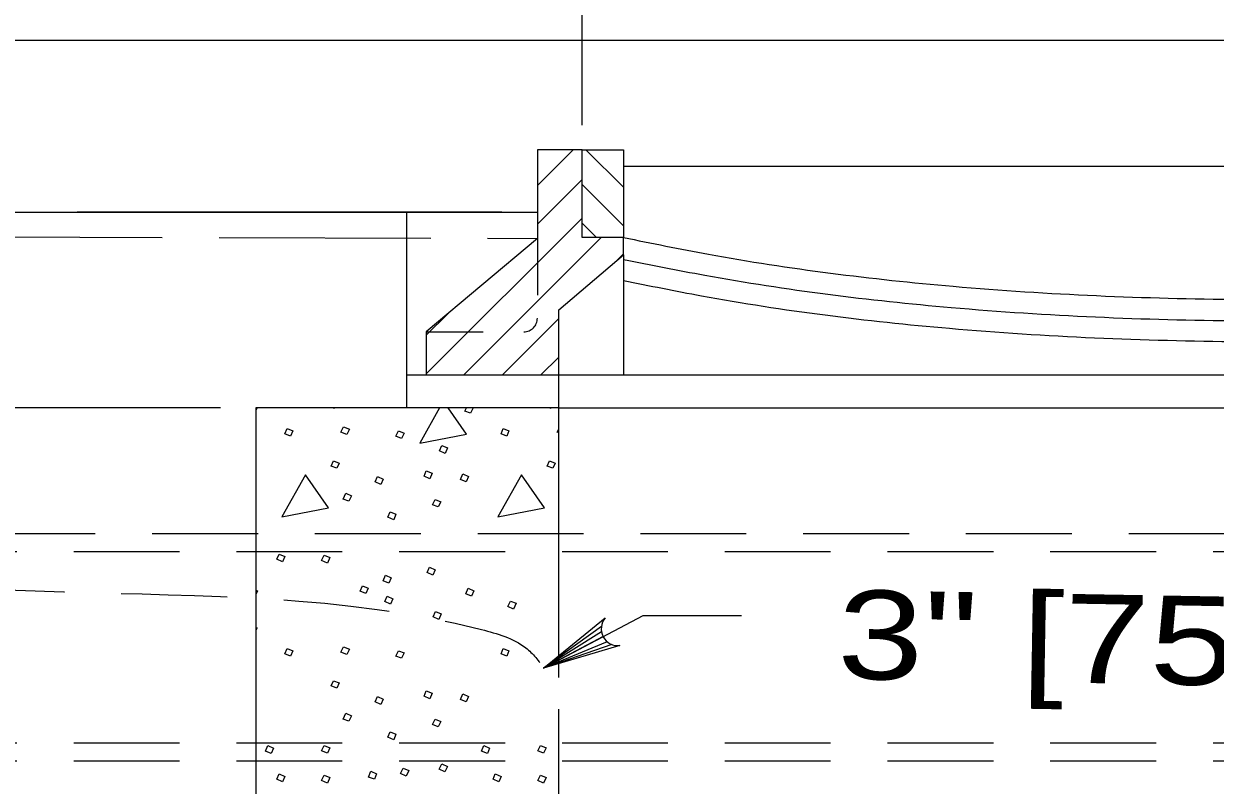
# Model space of a CAD drawing. Extents: x 1083.1 to 1123, y 697.4 to 741.4.
# Drawn here: x 1092.128 to 1094.221, y 724.717 to 726.055 of the extents above; entities that cross this region are included whole.
import ezdxf

# ---------------------------------------------------------------- set-up
doc = ezdxf.new("R2010")
doc.units = 0
doc.header["$LTSCALE"] = 0.062
for name, pattern in [('LONG_DASHED', [7.5, 6, -1.5]), ('MEDIUM_DASHED', [4.5, 3, -1.5]), ('SHORT_DASHED', [2.7, 1.5, -1.2])]:
    doc.linetypes.add(name, pattern=pattern)
doc.layers.add('1', color=7, linetype='Continuous', lineweight=13)

msp = doc.modelspace()

# ---------------------------------------------------------------- linework, layer by layer
at = {"layer": '1'}
for p, q in [((1093.10842, 725.87658), (1093.10842, 726.45525)), ((1093.02983, 725.77058), (1093.09258, 725.83325)), ((1093.18108, 725.7675), (1093.11533, 725.83325)), ((1093.02983, 725.70275), (1093.10842, 725.78125)), ((1093.18108, 725.69958), (1093.10842, 725.77225)), ((1092.8345, 725.4395), (1093.10842, 725.71342)), ((1093.13358, 725.67925), (1093.10842, 725.70442)), ((1092.9005, 725.43767), (1093.14208, 725.67925)), ((1093.18108, 725.67925), (1093.10842, 725.67925)), ((1093.16817, 725.6375), (1093.18108, 725.65042)), ((1092.8345, 725.50733), (1092.87292, 725.54583)), ((1092.96833, 725.43767), (1093.0675, 725.53683)), ((1093.03617, 725.43767), (1093.0675, 725.469)), ((1092.47292, 725.37967), (1091.73158, 725.37967)), ((1092.5375, 725.37967), (1092.53542, 725.37542)), ((1093.14242, 724.99583), (1093.04042, 724.9225)), ((1093.14267, 724.98625), (1093.04042, 724.9225)), ((1093.14567, 724.97792), (1093.04042, 724.9225)), ((1093.15275, 724.969), (1093.04042, 724.9225)), ((1093.16075, 724.96417), (1093.04042, 724.9225))]:
    msp.add_line(p, q, dxfattribs=at)
at = {"layer": '1', "lineweight": 25}
for p, q in [((1093.18108, 725.80433), (1095.37617, 725.80433)), ((1092.96733, 725.7235), (1092.22125, 725.7235)), ((1092.80058, 725.37967), (1092.80058, 725.7235)), ((1093.18108, 725.6485), (1093.18108, 725.43767)), ((1092.80058, 725.43767), (1092.8345, 725.43767)), ((1093.0675, 725.43767), (1095.37617, 725.43767)), ((1093.0675, 725.37967), (1095.442, 725.37967)), ((1093.0675, 724.90642), (1093.0675, 725.37967)), ((1093.0675, 722.82933), (1093.0675, 724.8505))]:
    msp.add_line(p, q, dxfattribs=at)
at = {"layer": '1', "linetype": 'LONG_DASHED', "lineweight": 25}
msp.add_line((1091.9985, 725.68033), (1093.02983, 725.67767), dxfattribs=at)
at = {"layer": '1', "linetype": 'SHORT_DASHED', "lineweight": 25}
for p, q in [((1093.02983, 725.67767), (1093.02983, 725.5375)), ((1092.8345, 725.5135), (1093.00583, 725.5135))]:
    msp.add_line(p, q, dxfattribs=at)
at = {"layer": '1', "linetype": 'MEDIUM_DASHED'}
for p, q in [((1089.92717, 725.12742), (1098.57942, 725.12742)), ((1089.92717, 724.79158), (1098.57942, 724.79158)), ((1089.92717, 724.75958), (1098.57942, 724.75958))]:
    msp.add_line(p, q, dxfattribs=at)
at = {"layer": '1', "lineweight": 25}
for points in [[(1098.22375, 725.23933), (1098.22375, 726.0255), (1090.30608, 726.0255)], [(1086.37042, 725.87725), (1090.30608, 725.7235), (1093.02983, 725.7235)], [(1093.10842, 725.83325), (1093.02983, 725.83325), (1093.02983, 725.67767), (1092.8345, 725.5135), (1092.8345, 725.43767), (1093.0675, 725.43767)], [(1093.10842, 725.67925), (1093.10842, 725.83325), (1093.18108, 725.83325), (1093.18108, 725.67925)], [(1093.0675, 725.37967), (1093.0675, 725.552), (1093.18108, 725.6485), (1093.18108, 725.67925)], [(1093.0675, 725.37967), (1092.53542, 725.37967), (1092.53542, 721.67958), (1095.96625, 721.67958), (1095.96625, 725.37967)]]:
    msp.add_lwpolyline(points, dxfattribs=at)
at = {"layer": '1'}
for points in [[(1092.67308, 725.37967), (1092.67283, 725.379), (1092.67117, 725.37967)], [(1092.858, 725.37967), (1092.82342, 725.31767), (1092.90533, 725.33367), (1092.87308, 725.37967)], [(1092.91733, 725.37967), (1092.91267, 725.37033), (1092.90267, 725.37433), (1092.90517, 725.37967)], [(1093.05292, 725.37967), (1093.05267, 725.379), (1093.051, 725.37967)], [(1093.0675, 725.33583), (1093.06458, 725.337), (1093.0675, 725.34275)], [(1092.53542, 725.05983), (1092.53817, 725.0585), (1092.53542, 725.052)], [(1093.04042, 724.9225), (1093.21592, 725.01492), (1093.38875, 725.01492)], [(1092.53542, 724.99417), (1092.5375, 724.99317), (1092.53542, 724.98892)], [(1093.17475, 724.96217), (1093.04042, 724.9225), (1093.14917, 725.01083)]]:
    msp.add_lwpolyline(points, dxfattribs=at)
for points in [[(1092.59017, 725.34367), (1092.60017, 725.33967), (1092.59617, 725.33033), (1092.58617, 725.33433)], [(1092.6895, 725.34633), (1092.6995, 725.34233), (1092.69483, 725.333), (1092.68483, 725.337)], [(1092.78608, 725.33967), (1092.79608, 725.33567), (1092.79142, 725.32633), (1092.78142, 725.33033)], [(1092.97, 725.34367), (1092.98, 725.33967), (1092.976, 725.33033), (1092.966, 725.33433)], [(1092.86208, 725.31367), (1092.87208, 725.30967), (1092.86808, 725.29967), (1092.85808, 725.30433)], [(1092.6715, 725.287), (1092.6815, 725.283), (1092.6775, 725.27367), (1092.6675, 725.27767)], [(1093.05133, 725.287), (1093.06133, 725.283), (1093.05733, 725.27367), (1093.04733, 725.27767)], [(1092.83475, 725.269), (1092.84475, 725.265), (1092.84075, 725.25508), (1092.83075, 725.25975)], [(1092.62217, 725.26233), (1092.58083, 725.18842), (1092.66283, 725.20442)], [(1092.74875, 725.25908), (1092.75875, 725.25442), (1092.75475, 725.24508), (1092.74475, 725.24975)], [(1092.89867, 725.26375), (1092.90867, 725.25908), (1092.90467, 725.24975), (1092.89467, 725.25375)], [(1093.002, 725.26233), (1092.96067, 725.18842), (1093.04267, 725.20442)], [(1092.6935, 725.22975), (1092.7035, 725.22508), (1092.69883, 725.21575), (1092.68883, 725.21975)], [(1092.85008, 725.21908), (1092.86008, 725.21508), (1092.85542, 725.20575), (1092.84542, 725.20975)], [(1092.77142, 725.19708), (1092.78142, 725.19308), (1092.77742, 725.18308), (1092.76742, 725.18775)], [(1092.57617, 725.12308), (1092.58617, 725.1185), (1092.58217, 725.10917), (1092.57217, 725.11383)], [(1092.6555, 725.12108), (1092.6655, 725.11708), (1092.66083, 725.10717), (1092.65083, 725.11183)], [(1092.84008, 725.09983), (1092.85008, 725.09517), (1092.84608, 725.08583), (1092.83608, 725.0905)], [(1092.76275, 725.08583), (1092.77275, 725.08117), (1092.76875, 725.07183), (1092.75875, 725.07583)], [(1092.72275, 725.06717), (1092.73275, 725.06317), (1092.72875, 725.05383), (1092.71875, 725.05783)], [(1092.908, 725.06317), (1092.918, 725.0585), (1092.914, 725.04917), (1092.904, 725.05317)], [(1092.76608, 725.04917), (1092.77608, 725.0445), (1092.77208, 725.03517), (1092.76208, 725.03983)], [(1092.98267, 725.0405), (1092.99267, 725.0365), (1092.988, 725.0265), (1092.978, 725.03117)], [(1092.85075, 725.02183), (1092.86075, 725.01783), (1092.85675, 725.00783), (1092.84675, 725.0125)], [(1092.59017, 724.95725), (1092.60017, 724.95325), (1092.59617, 724.94392), (1092.58617, 724.94792)], [(1092.6895, 724.95992), (1092.6995, 724.95592), (1092.69483, 724.94658), (1092.68483, 724.95058)], [(1092.78608, 724.95325), (1092.79608, 724.94925), (1092.79142, 724.93992), (1092.78142, 724.94392)], [(1092.97, 724.95725), (1092.98, 724.95325), (1092.976, 724.94392), (1092.966, 724.94792)], [(1092.6715, 724.90058), (1092.6815, 724.89658), (1092.6775, 724.88725), (1092.6675, 724.89125)], [(1092.74875, 724.87258), (1092.75875, 724.86792), (1092.75475, 724.85858), (1092.74475, 724.86325)], [(1092.83475, 724.88258), (1092.84475, 724.87858), (1092.84075, 724.86858), (1092.83075, 724.87325)], [(1092.89867, 724.87725), (1092.90867, 724.87258), (1092.90467, 724.86325), (1092.89467, 724.86725)], [(1092.6935, 724.84325), (1092.7035, 724.83858), (1092.69883, 724.82925), (1092.68883, 724.83325)], [(1092.85008, 724.83267), (1092.86008, 724.82858), (1092.85542, 724.81933), (1092.84542, 724.82333)], [(1092.77142, 724.81067), (1092.78142, 724.80667), (1092.77742, 724.79667), (1092.76742, 724.80133)], [(1092.55617, 724.78667), (1092.56617, 724.782), (1092.56217, 724.77267), (1092.55217, 724.77667)], [(1092.6555, 724.78667), (1092.6655, 724.78267), (1092.66083, 724.77333), (1092.65083, 724.77733)], [(1092.936, 724.78667), (1092.946, 724.782), (1092.942, 724.77267), (1092.932, 724.77667)], [(1093.03533, 724.78667), (1093.04533, 724.78267), (1093.04067, 724.77333), (1093.03067, 724.77733)], [(1092.73742, 724.74133), (1092.74742, 724.73667), (1092.74342, 724.72733), (1092.73342, 724.73133)], [(1092.79408, 724.74667), (1092.80408, 724.74267), (1092.79942, 724.73267), (1092.78942, 724.73733)], [(1092.86208, 724.75467), (1092.87208, 724.75), (1092.86742, 724.74067), (1092.85742, 724.74533)], [(1092.57617, 724.73667), (1092.58617, 724.732), (1092.58217, 724.72267), (1092.57217, 724.72733)], [(1092.6555, 724.73467), (1092.6655, 724.73067), (1092.66083, 724.72067), (1092.65083, 724.72533)], [(1092.956, 724.73667), (1092.966, 724.732), (1092.962, 724.72267), (1092.952, 724.72733)], [(1093.03533, 724.73467), (1093.04533, 724.73067), (1093.04067, 724.72067), (1093.03067, 724.72533)]]:
    msp.add_lwpolyline(points, close=True, dxfattribs=at)
at = {"layer": '1', "linetype": 'MEDIUM_DASHED'}
msp.add_lwpolyline([(1089.92717, 725.15933), (1092.067, 725.15933), (1098.57942, 725.15933)], dxfattribs=at)
at = {"layer": '1', "linetype": 'SHORT_DASHED', "lineweight": 25}
msp.add_ellipse((1093.00585, 725.53748), major_axis=(0.02399, 0), ratio=0.999895, start_param=4.712389, end_param=6.2831853, dxfattribs=at)
at = {"layer": '1'}
msp.add_ellipse((1093.17187, 724.99172), major_axis=(-0.02906, 0.00596), ratio=0.999895, start_param=5.7849266, end_param=8.1555398, dxfattribs=at)
at = {"layer": '1', "lineweight": 25}
for points in [[(1093.18108, 725.67925), (1093.33033, 725.64992), (1093.7605, 725.5935), (1094.26483, 725.5705), (1094.82308, 725.594), (1095.37617, 725.67925)], [(1093.1815, 725.64083), (1093.32425, 725.613), (1093.75725, 725.55625), (1094.26483, 725.533), (1094.82675, 725.55667), (1095.3765, 725.64133)], [(1093.18133, 725.60375), (1093.31833, 725.57683), (1093.754, 725.51967), (1094.26475, 725.49642), (1094.83025, 725.52025), (1095.3765, 725.60433)]]:
    msp.add_spline(points, degree=3, dxfattribs=at)
at = {"layer": '1', "linetype": 'MEDIUM_DASHED', "lineweight": 25}
msp.add_spline([(1090.30608, 725.23933), (1090.84817, 725.17692), (1092.198, 725.05667), (1092.9315, 724.9905), (1093.00942, 724.95833), (1093.04133, 724.92083), (1093.05967, 724.8775), (1093.06858, 724.84542)], degree=3, dxfattribs=at)

# ---------------------------------------------------------------- texts
at = {"layer": '1', "width": 1.3}
msp.add_text('3" [75] rad.', height=0.156, rotation=359, dxfattribs=at).set_placement((1093.55608, 724.90417))

doc.saveas('drawing.dxf')
